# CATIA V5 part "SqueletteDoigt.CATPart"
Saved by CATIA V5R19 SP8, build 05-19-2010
Part number: SqueletteDoigt
Bounding box of the stored display mesh (mm): x 0 to 20, y 28 to 91, z 60 to 60
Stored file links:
  C:\Users\rcousturie\Desktop\EU_thinkMotion\iao\IAO_MMS_Groupe1\abergami\abergami_catiaInitial\ObjetsInitials\SqueletteDoigt.CATPart
  C:\Users\rcousturie\Desktop\EU_thinkMotion\iao\IAO_MMS_Groupe1\abergami\abergami_catiaInitial\ObjetsInitials\Product2.CATProduct
  C:\Users\rcousturie\Desktop\EU_thinkMotion\iao\IAO_MMS_Groupe1\abergami\abergami_catiaInitial\ObjetsInitials\SqueletteCoulisse.CATPart
  C:\Users\rcousturie\Desktop\EU_thinkMotion\iao\IAO_MMS_Groupe1\abergami\abergami_catiaInitial\ObjetsInitials\Squelettedebase.CATPart
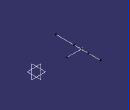
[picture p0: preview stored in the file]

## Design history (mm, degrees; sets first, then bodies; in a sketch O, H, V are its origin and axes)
Set1
  Line1: linked copy from another document
  Point1: linked copy from another document
Set2
  Line2: type Normal, RefPoint Point1, RefSkin yz-plane, Start 0, End 20
  Line3: type PtDir, RefPoint Point1, Direction Line1, Start -10, End 10
Body1 (main body)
